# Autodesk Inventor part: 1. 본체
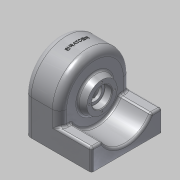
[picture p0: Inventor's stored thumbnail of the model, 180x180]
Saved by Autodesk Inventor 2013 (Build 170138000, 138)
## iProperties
Created: 2015-02
Part Number: 1. 본체
Material: 알루미늄 6061
Document SubType Name: Modeling
Designer: Administrator
Density: 1 g/cm^3
Author: Administrator
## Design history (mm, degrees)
sketch "스케치1"
  geometry: L1 (-25, 50)-(25, 50); L2 (25, 50)-(25, -50); L3 (25, -50)-(-25, -50); L4 (-25, -50)-(-25, 50); 3 further points
  constraints: 8 end point, 2 midpoint, 2 parallel, 1 horizontal, 1 horizontal alignment, 1 perpendicular, 1 vertical alignment
  dimensions: "d0" = 50 distance of L2.end L3.end; "d2" = 100 distance of L1.end L2.end
extrude "돌출1" new body sketch "스케치1" distance "d3" = 100; taper "d4" = 0 deg
fillet "모깎기1" dims "d5" = 50
sketch "스케치5"
  geometry: L1 (-35, 50)-(34, 50); L2 (-35, 50)-(-35, 71.36); L3 (-35, 71.36)-(-25, 75); L4 (-25, 50)-(-25, 100) reference; L5 (-25, 0)-(-25, 50) reference; L6 (25, 0)-(25, 50) reference; L7 (-25, 0)-(25, 0) reference; L8 (-25, 70)-(34, 70); L9 (34, 50)-(34, 70); L10 (-25, 75)-(-25, 75); L11 (-25, 75)-(-25, 70); 1 further point
  constraints: 14 end point, 4 perpendicular, 1 horizontal, 1 midpoint, 1 parallel, 1 point on line
  dimensions: "d28" = 10 distance from line of L5 L1.start; "d29" = 9 distance from line of L6 L1.end; "d30" = 50 distance between parallel lines of L7 L1; "d31" = 110 deg angle of L3 L4; "d32" = 50 diameter of L3.end L1; "d33" = 40 diameter of L8 L1
revolve "회전1" sketch "스케치5" stored, may be unused: angle "d34" = 90 deg
node "작업 평면1"
sketch "스케치6"
  geometry: L1 (0, 100)-(50, 100) reference; L2 (0, 0)-(50, 0) reference; L3 (0, 100)-(0, 0) reference; L4 (50, 4)-(0, 4); L5 (0, 96)-(50, 96); L6 (0, 96)-(0, 4); A1 r 50 centre (50, 50) between (50, 0) and (50, 100) reference; A2 r 46 centre (50, 50) between (50, 4) and (50, 96); 1 further point
  constraints: 6 end point, 2 point on circle, 2 point on line, 1 centre point, 1 collinear
  dimensions: "d35" = 4 radial gap between concentric circles of A1 A2; "d36" = 4 distance between parallel lines of L1 L5; "d37" = 4 distance between parallel lines of L2 L4
extrude "돌출3" cut sketch "스케치6" stored distance "d38" = 42; taper "d39" = 0 deg
hole "구멍1" diameter "d42" = 20; stored, may be unused: countersink angle "d46" = 90 deg, drill point angle "d48" = 0 deg; dims "d40" = 10, "d41" = 10, "d43" = 6, "d44" = 28, "d45" = 10, "d47" = 4
hole "구멍2" diameter "d51" = 20; stored, may be unused: countersink angle "d55" = 90 deg, drill point angle "d57" = 0 deg; dims "d49" = 10, "d50" = 10, "d52" = 6, "d53" = 28, "d54" = 8, "d56" = 2
sketch "스케치7"
  geometry: L1 (0, 0)-(-50, 0) reference; L2 (0, 100)-(0, 0) reference; L3 (0, 100)-(-50, 100) reference; L4 (-30, 100)-(0, 100); L5 (-30, 100)-(-30, 84.641); L6 (0, 0)-(-30, 0); L7 (-30, 0)-(-30, 15.359); A1 r 50 centre (-50, 50) between (-50, 100) and (-50, 0) reference; A2 r 40 centre (-50, 50) between (-30, 15.359) and (-30, 84.641); 1 further point
  constraints: 8 end point, 2 collinear, 2 perpendicular, 2 point on circle, 2 point on line, 1 centre point, 1 coincident
  dimensions: "d58" = 80 diameter of A2; "d59" = 30 distance of L4.start L2.start
extrude "돌출4" join sketch "스케치7" distance "d60" = 45; taper "d61" = 0 deg
sketch "스케치8"
  geometry: L1 (-70, -50)-(-70, 50) reference; L2 (25, -50)-(25, 50) reference; L3 (-61, 41.75)-(-61, -41.75); 4 further points
  constraints: 3 horizontal alignment, 2 end point, 2 vertical alignment, 1 midpoint, 1 parallel
  dimensions: "d62" = 33 distance of point (-28, 41.75) L3.start; "d64" = 9 distance from line of L1 L3.start; "d65" = 83.5 distance of L3.end L3.start
hole "구멍3" sketch "스케치8" at (-61, 41.75), (-28, 41.75), (-28, -41.75), (-61, -41.75) diameter "d66" = 5.134; stored, may be unused: countersink angle "d70" = 90 deg, drill point angle "d72" = 118 deg; dims "d67" = 10, "d68" = 4, "d69" = 2, "d71" = 13
sketch "스케치9" dims "d73" = 36
  geometry: C1 r 14 at (0, 0) reference; C2 r 21.36 at (0, 0) reference; 3 further points
  constraints: 2 horizontal alignment, 1 coincident, 2 other
hole "구멍4" sketch "스케치9" at (-18, 0) diameter "d74" = 2.459; stored, may be unused: countersink angle "d78" = 90 deg, drill point angle "d80" = 118 deg; dims "d75" = 6, "d76" = 4, "d77" = 2, "d79" = 9
fillet "모깎기2" dims "d84" = 10
fillet "모깎기3" dims "d85" = 6
fillet "모깎기4" dims "d86" = 0.3
fillet "모깎기5" dims "d87" = 3
chamfer "모따기1" distance "d88" = 1; stored, may be unused: second distance "d89" = 2, angle "d90" = 45 deg
node "작업 평면2"
sketch "스케치10"
  geometry: L1 (-2.5, 50)-(-2.5, -50) reference; L2 (-12.5, -40)-(-12.5, 40) reference; 3 further points
  constraints: 1 midpoint, 1 other
  dimensions: "d91" = 25 distance from line of point (12.5, 0) L2
feature "엠보싱1" sketch "스케치10" dims "d0" = 50, "d2" = 100, "d92" = 0.5, "d93" = 0
node "솔리드1"
pattern_circular "원형 패턴1" dims angle "d82" = 360 deg
